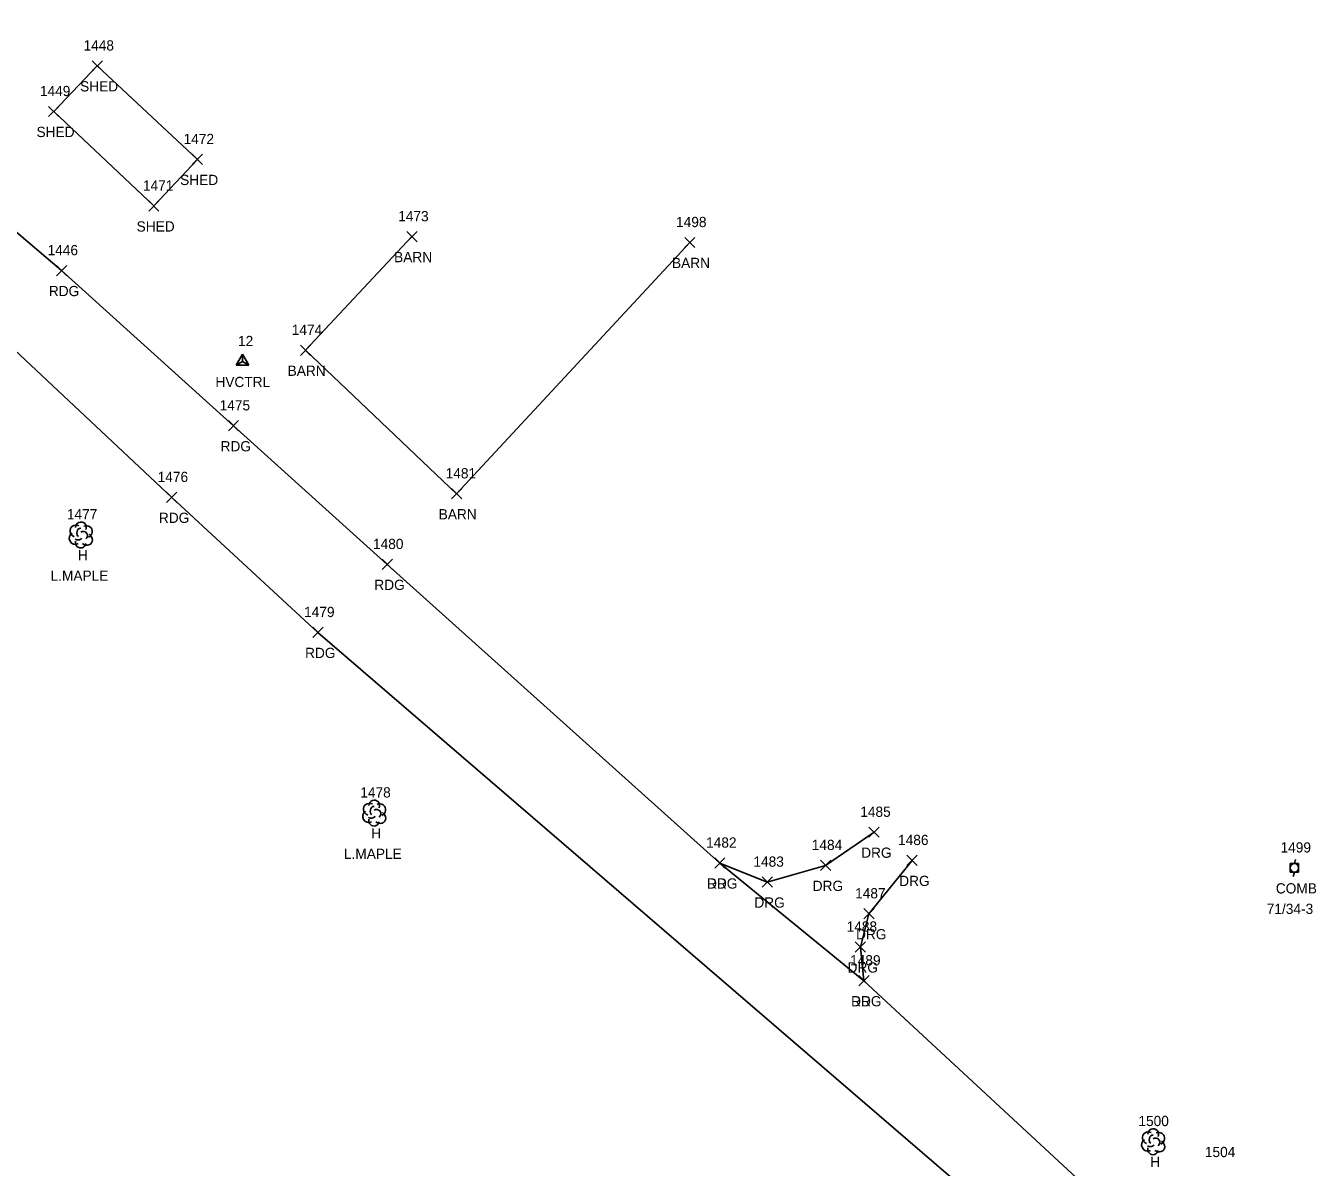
# Model space of a CAD drawing. Extents: x 1496556 to 1498241, y 599216 to 604470.
# Drawn here: x 1497084.6 to 1497336.6, y 603628.4 to 603851.4 of the extents above; entities that cross this region are included whole.
import ezdxf

# ---------------------------------------------------------------- set-up
doc = ezdxf.new("R2010")
doc.units = 0
for name, color, linetype in [('C_A', 7, 'Continuous'), ('C_I', 7, 'Continuous'), ('CPSM', 7, 'Continuous'), ('L_A', 7, 'Continuous'), ('L_C', 7, 'Continuous'), ('L_I', 7, 'Continuous'), ('L_TIC', 7, 'Continuous'), ('LBC', 7, 'Continuous'), ('LTD', 7, 'Continuous'), ('P_A', 7, 'Continuous'), ('P_I', 7, 'Continuous'), ('P_TIC', 7, 'Continuous'), ('PEU', 7, 'Continuous'), ('R_A', 7, 'Continuous'), ('R_I', 7, 'Continuous'), ('R_TIC', 7, 'Continuous'), ('RDG', 7, 'Continuous'), ('U_A', 7, 'Continuous'), ('U_C', 7, 'Continuous'), ('U_I', 7, 'Continuous'), ('UP', 7, 'Continuous')]:
    doc.layers.add(name, color=color, linetype=linetype)

msp = doc.modelspace()

# ---------------------------------------------------------------- linework, layer by layer
at = {"layer": 'CPSM'}
for p, q in [((1497125.65, 603785.1), (1497126.9, 603787.27)), ((1497128.15, 603785.1), (1497126.9, 603787.27)), ((1497126.9, 603785.82), (1497126.9, 603787.27)), ((1497125.65, 603785.1), (1497126.9, 603785.82)), ((1497125.65, 603785.1), (1497128.15, 603785.1)), ((1497126.9, 603785.82), (1497126.9, 603785.82)), ((1497126.9, 603785.82), (1497128.15, 603785.1))]:
    msp.add_line(p, q, dxfattribs=at)
at = {"layer": 'L_TIC'}
for points in [[(1497097.52, 603842.57), (1497099.52, 603844.57)], [(1497099.52, 603842.57), (1497097.52, 603844.57)], [(1497097.52, 603842.57), (1497099.52, 603844.57)], [(1497099.52, 603842.57), (1497097.52, 603844.57)], [(1497089.01, 603833.66), (1497091.01, 603835.66)], [(1497091.01, 603833.66), (1497089.01, 603835.66)], [(1497117.06, 603824.29), (1497119.06, 603826.29)], [(1497119.06, 603824.29), (1497117.06, 603826.29)], [(1497117.06, 603824.29), (1497119.06, 603826.29)], [(1497119.06, 603824.29), (1497117.06, 603826.29)], [(1497108.56, 603815.2), (1497110.56, 603817.2)], [(1497110.56, 603815.2), (1497108.56, 603817.2)], [(1497158.98, 603809.21), (1497160.98, 603811.21)], [(1497160.98, 603809.21), (1497158.98, 603811.21)], [(1497158.98, 603809.21), (1497160.98, 603811.21)], [(1497160.98, 603809.21), (1497158.98, 603811.21)], [(1497213.25, 603808.07), (1497215.25, 603810.07)], [(1497215.25, 603808.07), (1497213.25, 603810.07)], [(1497138.19, 603787.01), (1497140.19, 603789.01)], [(1497140.19, 603787.01), (1497138.19, 603789.01)], [(1497167.69, 603758.98), (1497169.69, 603760.98)], [(1497169.69, 603758.98), (1497167.69, 603760.98)]]:
    msp.add_lwpolyline(points, dxfattribs=at)
at = {"layer": 'LBC'}
for points in [[(1497098.52, 603843.57), (1497090.01, 603834.66), (1497109.56, 603816.2), (1497118.06, 603825.29)], [(1497098.52, 603843.57), (1497118.06, 603825.29)], [(1497159.98, 603810.21), (1497139.19, 603788.01), (1497168.69, 603759.98), (1497214.25, 603809.07)]]:
    msp.add_lwpolyline(points, dxfattribs=at)
at = {"layer": 'LTD'}
for p, q in [((1497095.28, 603751.98), (1497095.28, 603751.98)), ((1497095.28, 603751.98), (1497095.28, 603751.98)), ((1497152.58, 603697.64), (1497152.58, 603697.64)), ((1497152.58, 603697.64), (1497152.58, 603697.64)), ((1497304.73, 603633.45), (1497304.73, 603633.45)), ((1497304.73, 603633.45), (1497304.73, 603633.45))]:
    msp.add_line(p, q, dxfattribs=at)
for centre in [(1497095.32, 603753.41), (1497152.63, 603699.07), (1497304.77, 603634.88)]:
    msp.add_arc(centre, 1.05, 335.5272, 180.9563, dxfattribs=at)
for centre, major_axis, ratio, start_param, end_param in [((1497094.48, 603752.65), (1.21, -0.51), 0.895232, 1.570796, 4.712389), ((1497096.32, 603752.56), (-1.14, -0.48), 0.949671, 1.570796, 4.712389), ((1497094.19, 603751.27), (0.58, -1.04), 0.959034, 3.141593, 6.283185), ((1497094.82, 603751.23), (-0.625, -0.083), 0.423636, 0, 3.141593), ((1497095.07, 603752.44), (-0.208, -0.792), 0.645439, 3.141593, 6.283185), ((1497095.78, 603751.81), (-0.5, 0.667), 0.989748, 3.141593, 6.283185), ((1497096.28, 603751.15), (-1.09, 0.79), 0.841452, 1.570796, 4.712389), ((1497095.28, 603750.48), (0.26, 1.06), 0.942809, 1.570796, 4.712389), ((1497151.79, 603698.3), (1.21, -0.51), 0.895232, 1.570796, 4.712389), ((1497152.37, 603698.09), (-0.208, -0.792), 0.645439, 3.141593, 6.283185), ((1497153.08, 603697.47), (-0.5, 0.667), 0.989748, 3.141593, 6.283185), ((1497153.62, 603698.22), (-1.14, -0.48), 0.949671, 1.570796, 4.712389), ((1497151.5, 603696.93), (0.58, -1.04), 0.959034, 3.141593, 6.283185), ((1497152.58, 603696.14), (0.26, 1.06), 0.942809, 1.570796, 4.712389), ((1497152.12, 603696.89), (-0.625, -0.083), 0.423636, 0, 3.141593), ((1497153.58, 603696.8), (-1.09, 0.79), 0.841452, 1.570796, 4.712389), ((1497303.93, 603634.11), (1.21, -0.51), 0.895232, 1.570796, 4.712389), ((1497305.77, 603634.03), (-1.14, -0.48), 0.949671, 1.570796, 4.712389), ((1497303.64, 603632.74), (0.58, -1.04), 0.959034, 3.141593, 6.283185), ((1497304.27, 603632.7), (-0.625, -0.083), 0.423636, 0, 3.141593), ((1497304.52, 603633.9), (-0.208, -0.792), 0.645439, 3.141593, 6.283185), ((1497305.23, 603633.28), (-0.5, 0.667), 0.989748, 3.141593, 6.283185), ((1497305.73, 603632.61), (-1.09, 0.79), 0.841452, 1.570796, 4.712389), ((1497304.73, 603631.95), (0.26, 1.06), 0.942809, 1.570796, 4.712389)]:
    msp.add_ellipse(centre, major_axis=major_axis, ratio=ratio, start_param=start_param, end_param=end_param, dxfattribs=at)
at = {"layer": 'P_TIC'}
for points in [[(1497090.56, 603802.58), (1497092.56, 603804.58)], [(1497092.56, 603802.58), (1497090.56, 603804.58)], [(1497124.12, 603772.26), (1497126.12, 603774.26)], [(1497126.12, 603772.26), (1497124.12, 603774.26)], [(1497112.06, 603758.28), (1497114.06, 603760.28)], [(1497114.06, 603758.28), (1497112.06, 603760.28)], [(1497154.15, 603745.18), (1497156.15, 603747.18)], [(1497156.15, 603745.18), (1497154.15, 603747.18)], [(1497140.61, 603731.89), (1497142.61, 603733.89)], [(1497142.61, 603731.89), (1497140.61, 603733.89)], [(1497219.12, 603686.84), (1497221.12, 603688.84)], [(1497221.12, 603686.84), (1497219.12, 603688.84)], [(1497247.27, 603663.84), (1497249.27, 603665.84)], [(1497249.27, 603663.84), (1497247.27, 603665.84)]]:
    msp.add_lwpolyline(points, dxfattribs=at)
at = {"layer": 'PEU'}
for points in [[(1496859.85, 603799.39), (1496865.05, 603796.5), (1496873.7, 603792.31), (1496883.54, 603793.48), (1496900.05, 603803.04), (1496919.62, 603816.41), (1496939.61, 603828.85), (1496964, 603841.16), (1496990.45, 603851.4), (1497013.22, 603849.84), (1497044.46, 603840.34), (1497066.94, 603824.52), (1497091.56, 603803.58), (1497125.12, 603773.26), (1497155.15, 603746.18), (1497220.12, 603687.84), (1497248.27, 603664.84), (1497294.22, 603622.27), (1497317.74, 603605), (1497324.77, 603590.17), (1497316.71, 603584.14), (1497305.64, 603569), (1497293.3, 603576.17)], [(1496891.52, 603741.51), (1496889.64, 603752.03), (1496894.84, 603769.23), (1496909.5, 603785.77), (1496931.96, 603802.73), (1496947.22, 603814.86), (1496973.09, 603827.29), (1496989.78, 603833.32), (1497015.57, 603832.12), (1497035.93, 603825.14), (1497055.45, 603810.85), (1497079.12, 603791.1), (1497113.06, 603759.28), (1497141.61, 603732.89), (1497273.63, 603619.21), (1497293.31, 603600.75), (1497297.23, 603588.2), (1497293.3, 603576.17)]]:
    msp.add_lwpolyline(points, dxfattribs=at)
at = {"layer": 'R_TIC'}
for points in [[(1497249.23, 603692.86), (1497251.23, 603694.86)], [(1497251.23, 603692.86), (1497249.23, 603694.86)], [(1497219.12, 603686.84), (1497221.12, 603688.84)], [(1497221.12, 603686.84), (1497219.12, 603688.84)], [(1497239.77, 603686.38), (1497241.77, 603688.38)], [(1497241.77, 603686.38), (1497239.77, 603688.38)], [(1497256.67, 603687.35), (1497258.67, 603689.35)], [(1497258.67, 603687.35), (1497256.67, 603689.35)], [(1497228.37, 603683.12), (1497230.37, 603685.12)], [(1497230.37, 603683.12), (1497228.37, 603685.12)], [(1497248.23, 603676.93), (1497250.23, 603678.93)], [(1497250.23, 603676.93), (1497248.23, 603678.93)], [(1497246.57, 603670.43), (1497248.57, 603672.43)], [(1497248.57, 603670.43), (1497246.57, 603672.43)], [(1497247.27, 603663.84), (1497249.27, 603665.84)], [(1497249.27, 603663.84), (1497247.27, 603665.84)]]:
    msp.add_lwpolyline(points, dxfattribs=at)
at = {"layer": 'RDG'}
for points in [[(1497220.12, 603687.84), (1497229.37, 603684.12), (1497240.77, 603687.38), (1497250.23, 603693.86)], [(1497257.67, 603688.35), (1497249.23, 603677.93), (1497247.57, 603671.43), (1497248.27, 603664.84)]]:
    msp.add_lwpolyline(points, dxfattribs=at)
at = {"layer": 'UP'}
for p, q in [((1497332.58, 603688.56), (1497332.33, 603687.72)), ((1497331.49, 603686.06), (1497331.49, 603687.72)), ((1497331.49, 603687.72), (1497333.16, 603687.72)), ((1497333.16, 603686.06), (1497331.49, 603686.06)), ((1497332.08, 603685.22), (1497332.33, 603686.06)), ((1497332.33, 603686.89), (1497332.33, 603686.89)), ((1497333.16, 603687.72), (1497333.16, 603686.06))]:
    msp.add_line(p, q, dxfattribs=at)
msp.add_circle((1497332.33, 603686.89), 0.833, dxfattribs=at)

# ---------------------------------------------------------------- texts
at = {"layer": 'C_A'}
msp.add_text('HVCTRL', height=2, dxfattribs=at).set_placement((1497121.59, 603780.82))
at = {"layer": 'C_I'}
msp.add_text('12', height=2, dxfattribs=at).set_placement((1497126, 603788.82))
at = {"layer": 'L_A'}
for s, p in [('SHED', (1497095.16, 603838.57)), ('SHED', (1497095.16, 603838.57)), ('SHED', (1497086.65, 603829.66)), ('SHED', (1497114.7, 603820.29)), ('SHED', (1497114.7, 603820.29)), ('SHED', (1497106.2, 603811.2)), ('BARN', (1497156.49, 603805.21)), ('BARN', (1497156.49, 603805.21)), ('BARN', (1497210.77, 603804.07)), ('BARN', (1497135.7, 603783.01)), ('BARN', (1497165.2, 603754.98)), ('H', (1497094.71, 603746.98)), ('H', (1497152.01, 603692.64)), ('H', (1497304.16, 603628.45))]:
    msp.add_text(s, height=2, dxfattribs=at).set_placement(p)
at = {"layer": 'L_C'}
for p in [(1497089.39, 603742.98), (1497146.69, 603688.64)]:
    msp.add_text('L.MAPLE', height=2, dxfattribs=at).set_placement(p)
at = {"layer": 'L_I'}
for s, p in [('1448', (1497095.83, 603846.57)), ('1448', (1497095.83, 603846.57)), ('1449', (1497087.31, 603837.66)), ('1472', (1497115.37, 603828.29)), ('1472', (1497115.37, 603828.29)), ('1471', (1497107.43, 603819.2)), ('1473', (1497157.29, 603813.21)), ('1473', (1497157.29, 603813.21)), ('1498', (1497211.56, 603812.07)), ('1474', (1497136.5, 603791.01)), ('1481', (1497166.56, 603762.98)), ('1477', (1497092.58, 603754.98)), ('1478', (1497149.89, 603700.64)), ('1500', (1497301.87, 603636.45))]:
    msp.add_text(s, height=2, dxfattribs=at).set_placement(p)
at = {"layer": 'P_A'}
for p in [(1497089.05, 603798.58), (1497122.6, 603768.26), (1497110.55, 603754.28), (1497152.63, 603741.18), (1497139.1, 603727.89), (1497217.61, 603682.84), (1497245.75, 603659.84)]:
    msp.add_text('RDG', height=2, dxfattribs=at).set_placement(p)
at = {"layer": 'P_I'}
for s, p in [('1446', (1497088.81, 603806.58)), ('1475', (1497122.42, 603776.26)), ('1476', (1497110.31, 603762.28)), ('1480', (1497152.37, 603749.18)), ('1479', (1497138.91, 603735.89)), ('1482', (1497217.43, 603690.84)), ('1489', (1497245.56, 603667.84))]:
    msp.add_text(s, height=2, dxfattribs=at).set_placement(p)
at = {"layer": 'R_A'}
for p in [(1497247.72, 603688.86), (1497217.61, 603682.84), (1497238.25, 603682.38), (1497255.15, 603683.35), (1497226.86, 603679.12), (1497246.72, 603672.93), (1497245.06, 603666.43), (1497245.75, 603659.84)]:
    msp.add_text('DRG', height=2, dxfattribs=at).set_placement(p)
at = {"layer": 'R_I'}
for s, p in [('1485', (1497247.54, 603696.86)), ('1486', (1497254.92, 603691.35)), ('1482', (1497217.43, 603690.84)), ('1484', (1497238.07, 603690.38)), ('1483', (1497226.67, 603687.12)), ('1487', (1497246.54, 603680.93)), ('1488', (1497244.88, 603674.43)), ('1489', (1497245.56, 603667.84)), ('1504', (1497314.85, 603630.39))]:
    msp.add_text(s, height=2, dxfattribs=at).set_placement(p)
at = {"layer": 'U_A'}
msp.add_text('COMB', height=2, dxfattribs=at).set_placement((1497328.71, 603681.89))
at = {"layer": 'U_C'}
msp.add_text('71/34-3', height=2, dxfattribs=at).set_placement((1497326.94, 603677.89))
at = {"layer": 'U_I'}
msp.add_text('1499', height=2, dxfattribs=at).set_placement((1497329.63, 603689.89))

doc.saveas('drawing.dxf')
